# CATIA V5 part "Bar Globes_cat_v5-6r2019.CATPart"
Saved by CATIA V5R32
Part number: Bar Globes
Bounding box of the stored display mesh (mm): x -5.91 to 5.91, y -4.926 to 5, z -5.992 to 5.992
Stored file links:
  D:\PROJECTS\Project 2022\CATIA V5 6R 2022\Resources\Tutorial Files\c16_catia_v5_6r2022_tut\Bench vice\Bar Globes_cat_v5-6r2019.CATPart
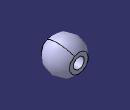
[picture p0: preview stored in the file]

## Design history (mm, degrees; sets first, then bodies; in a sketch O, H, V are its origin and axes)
Body1 (main body)
  Sketch1 on yz-plane, origin (0, 0, 0), H (0, 1, 0), V (0, 0, 1)
    arc A1 centre (0, 0) radius 6 from (6, 0) to (-6, 0) ccw
    line L1 (-6, 0) -> (6, 0)
    radius A1 = 6
    horizontal: L1 H
    coincidence: H L1
  Shaft1: profile Sketch1, axis edge of Sketch1, angle 360
  Sketch2 on yz-plane, origin (0, 0, 0), H (0, 1, 0), V (0, 0, 1)
    line L1 (-5, 7.2498) -> (5, 7.2498)
    line L2 (5, 7.2498) -> (5, -8.5554)
    line L3 (5, -8.5554) -> (1.27, -8.5554)
    line L4 (-5, -8.5554) -> (-5, 7.2498)
    line L5 (1.27, -8.5554) -> (1.27, -9.941)
    line L6 (1.27, -9.941) -> (8.2768, -9.941)
    line L7 (8.2768, -9.941) -> (8.2768, 9.8096)
    line L8 (8.2768, 9.8096) -> (-8.9775, 9.8096)
    line L9 (-8.9775, 9.8096) -> (-8.9775, -10.3789)
    line L10 (-8.9775, -10.3789) -> (-2.0145, -10.3789)
    line L11 (-2.0145, -10.3789) -> (-2.0145, -8.5554)
    point P12 (-2.0145, -8.5554)
    line L12 (-2.0145, -8.5554) -> (-5, -8.5554)
    length L1 = 10
    distance V L4 = 5
    horizontal: L1 H, L3 H, L6 H, L8 H, L10 H, L12 H
    vertical: L2 V, L4 V, L5 V, L7 V, L9 V, L11 V
    coincidence: P12 L3, L3 L12
  Pocket1: profile Sketch2, direction (-1, 0, 0), length 20, mirrored extent
  Sketch3 on face of Pocket1, origin (0.8583, -5, 1.5686), H (1, 0, 0), V (0, 0, 1)
    point P1 (-0.8583, -1.5686)
    reference intersected line E1 through (0, -1.5686) direction (-1, 0) from xy-plane
    reference intersected line E2 through (-0.8583, 0) direction (0, 1) from yz-plane
    coincidence: P1 E1, E2 P1
  Hole1: placed by Sketch3, at (0, -5, 0) direction (0, 1, 0), diameter 4, depth 10, countersink depth 1.5, countersink angle 90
